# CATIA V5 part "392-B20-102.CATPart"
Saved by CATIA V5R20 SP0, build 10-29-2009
Part number: 392-B20-102
Definition: NONE
Nomenclature: 392-B20-102
Source: Unknown
Description: 392-B20-102
Bounding box of the stored display mesh (mm): x 0 to 102, y -9.275 to 9.275, z -9.2 to 9.2
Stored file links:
  C:\Users\Utente\Desktop\IO LAVORO\3D X SITO CF\X SITO\3D files 392B\392-B20-102.CATPart
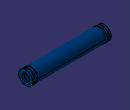
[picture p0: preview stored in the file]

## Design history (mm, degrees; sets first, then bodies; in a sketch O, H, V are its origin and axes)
Body1 "392-B20-102" (main body)
  Solid1: solid without history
